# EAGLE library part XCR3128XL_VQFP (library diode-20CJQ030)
Xilinx's XCR3128XL 128 Macrocell CPLD Features: Low power 3.3V 128 macrocell CPLD 6.0 ns pin-to-pin logic delays System frequencies up to 175 MHz 128 macrocells with 3,000 usable gates Available in small footprint packages -144-pin TQFP (108 user I/O pins) - 144-ball CS BGA (108 user I/O) - 100-pin VQFP (84 user I/O) Optimized for 3.3V systems - Ultra low power operation - 5V tolerant I/O pins with 3.3V core supply - Advanced 0.35 micron five layer metal EEPROM process - Fast Zero Power? (FZP) CMOS design technology - 3.3V PCI electrical specification compatible outputs (no internal clamp diode on any input or I/O) Advanced system features - In-system programming - Input registers - Predictable timing model - Up to 23 available clocks per function block - Excellent pin retention during design changes - Full IEEE Standard 1149.1 boundary-scan (JTAG) - Four global clocks - Eight product term control terms per function block Fast ISP programming times Port Enable pin for additional I/O 2.7V to 3.6V supply voltage at industrial temperature range Programmable slew rate control per output Security bit prevents unauthorized access Refer to XPLA3 family data sheet (DS012) for architecture description Description: The XCR3128XL is a 3.3V 128 macrocell CPLD targeted at power sensitive designs that require leading edge programmable logic solutions. A total of eight function blocks provide 3,000 usable gates. Pin-to-pin propagation delays are 6.0 ns with a maximum system frequency of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
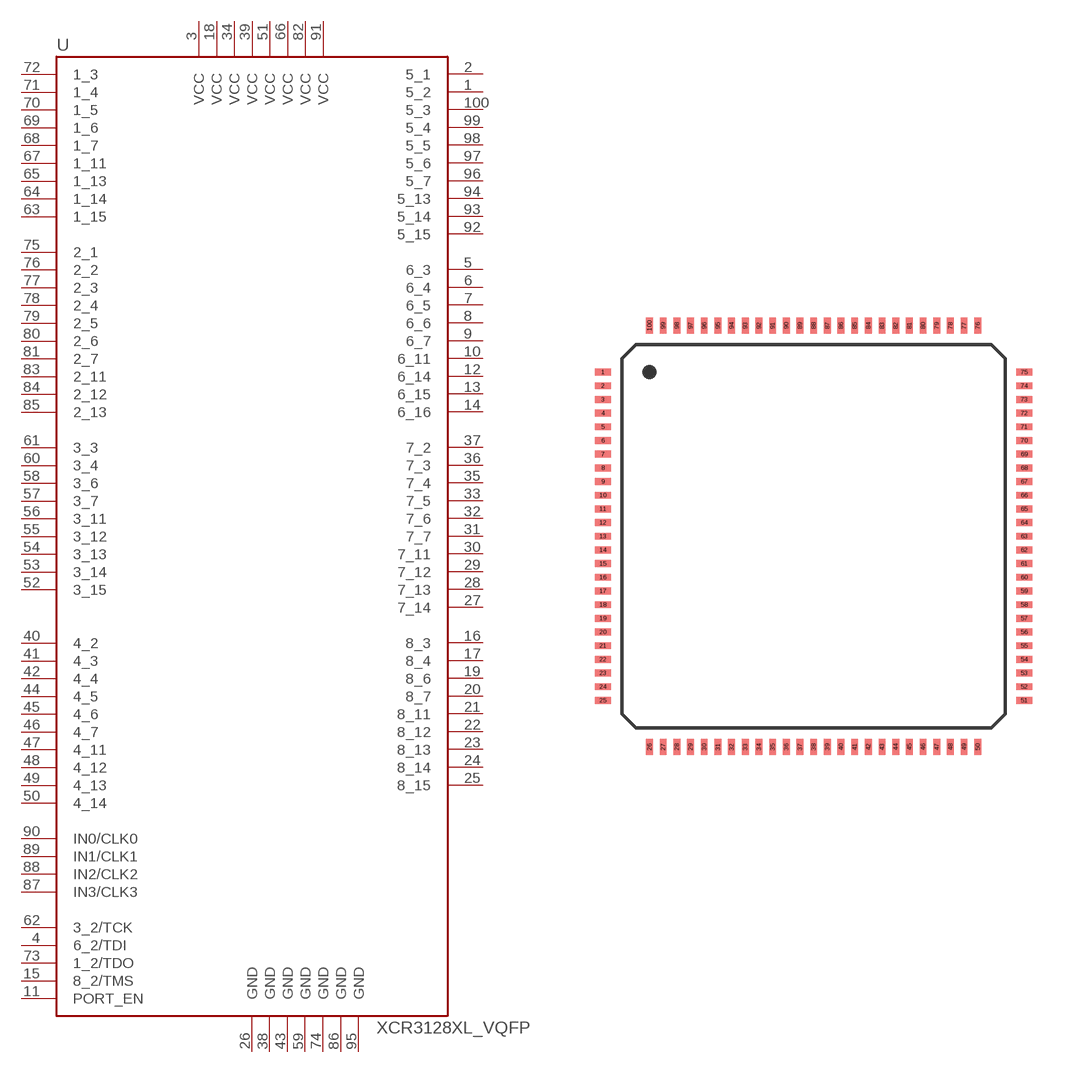
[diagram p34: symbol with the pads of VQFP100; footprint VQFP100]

Designator prefix U

## XCR3128XL_VQFP  [VQFP100]
1  5_2
2  5_1
3  VCC  pwr
4  6_2/TDI
5  6_3
6  6_4
7  6_5
8  6_6
9  6_7
10  6_11
11  PORT_EN  in
12  6_14
13  6_15
14  6_16
15  8_2/TMS
16  8_3
17  8_4
18  VCC  pwr
19  8_6
20  8_7
21  8_11
22  8_12
23  8_13
24  8_14
25  8_15
26  GND  pwr
27  7_14
28  7_13
29  7_12
30  7_11
31  7_7
32  7_6
33  7_5
34  VCC  pwr
35  7_4
36  7_3
37  7_2
38  GND  pwr
39  VCC  pwr
40  4_2
41  4_3
42  4_4
43  GND  pwr
44  4_5
45  4_6
46  4_7
47  4_11
48  4_12
49  4_13
50  4_14
51  VCC  pwr
52  3_15
53  3_14
54  3_13
55  3_12
56  3_11
57  3_7
58  3_6
59  GND  pwr
60  3_4
61  3_3
62  3_2/TCK
63  1_15
64  1_14
65  1_13
66  VCC  pwr
67  1_11
68  1_7
69  1_6
70  1_5
71  1_4
72  1_3
73  1_2/TDO
74  GND  pwr
75  2_1
76  2_2
77  2_3
78  2_4
79  2_5
80  2_6
81  2_7
82  VCC  pwr
83  2_11
84  2_12
85  2_13
86  GND  pwr
87  IN3/CLK3
88  IN2/CLK2
89  IN1/CLK1
90  IN0/CLK0
91  VCC  pwr
92  5_15
93  5_14
94  5_13
95  GND  pwr
96  5_7
97  5_6
98  5_5
99  5_4
100  5_3

## Footprint VQFP100 (pad centres in mm)
VQFP (VQ/VQG 100 Pin) Packages - Pitch: 0.5 mm - Pad-length : 0.6mm - Pad-Width : 0.22mm (0.25) Please send any comments to: messi@users.sourceforge.net
smd 0.6 x 0.25: 1 -7.7,6; 2 -7.7,5.5; 3 -7.7,5; 4 -7.7,4.5; 5 -7.7,4; 6 -7.7,3.5; 7 -7.7,3; 8 -7.7,2.5; 9 -7.7,2; 10 -7.7,1.5; 11 -7.7,1; 12 -7.7,0.5; 13 -7.7,0; 14 -7.7,-0.5; 15 -7.7,-1; 16 -7.7,-1.5; 17 -7.7,-2; 18 -7.7,-2.5; 19 -7.7,-3; 20 -7.7,-3.5; 21 -7.7,-4; 22 -7.7,-4.5; 23 -7.7,-5; 24 -7.7,-5.5; 25 -7.7,-6; 51 7.7,-6; 52 7.7,-5.5; 53 7.7,-5; 54 7.7,-4.5; 55 7.7,-4; 56 7.7,-3.5; 57 7.7,-3; 58 7.7,-2.5; 59 7.7,-2; 60 7.7,-1.5; 61 7.7,-1; 62 7.7,-0.5; 63 7.7,0; 64 7.7,0.5; 65 7.7,1; 66 7.7,1.5; 67 7.7,2; 68 7.7,2.5; 69 7.7,3; 70 7.7,3.5; 71 7.7,4; 72 7.7,4.5; 73 7.7,5; 74 7.7,5.5; 75 7.7,6
smd 0.25 x 0.6: 26 -6,-7.7; 27 -5.5,-7.7; 28 -5,-7.7; 29 -4.5,-7.7; 30 -4,-7.7; 31 -3.5,-7.7; 32 -3,-7.7; 33 -2.5,-7.7; 34 -2,-7.7; 35 -1.5,-7.7; 36 -1,-7.7; 37 -0.5,-7.7; 38 0,-7.7; 39 0.5,-7.7; 40 1,-7.7; 41 1.5,-7.7; 42 2,-7.7; 43 2.5,-7.7; 44 3,-7.7; 45 3.5,-7.7; 46 4,-7.7; 47 4.5,-7.7; 48 5,-7.7; 49 5.5,-7.7; 50 6,-7.7; 76 6,7.7; 77 5.5,7.7; 78 5,7.7; 79 4.5,7.7; 80 4,7.7; 81 3.5,7.7; 82 3,7.7; 83 2.5,7.7; 84 2,7.7; 85 1.5,7.7; 86 1,7.7; 87 0.5,7.7; 88 0,7.7; 89 -0.5,7.7; 90 -1,7.7; 91 -1.5,7.7; 92 -2,7.7; 93 -2.5,7.7; 94 -3,7.7; 95 -3.5,7.7; 96 -4,7.7; 97 -4.5,7.7; 98 -5,7.7; 99 -5.5,7.7; 100 -6,7.7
